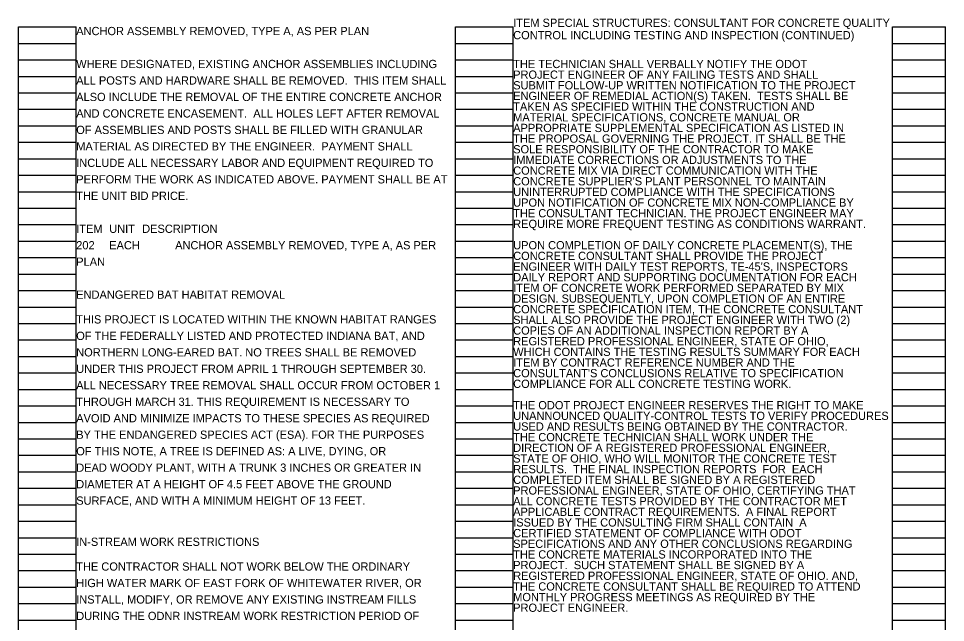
# Model space of a CAD drawing. Extents: x 0 to 78.9, y -24.2 to 22.
# Drawn here: x 61.9 to 77.64, y -13.19 to -2.93 of the extents above; entities that cross this region are included whole.
import ezdxf

# ---------------------------------------------------------------- set-up
doc = ezdxf.new("R2010")
doc.units = 0
doc.layers.add('SH_Data', color=7, linetype='Continuous')
doc.layers.add('SH_Text', color=7, linetype='Continuous')

msp = doc.modelspace()

# ---------------------------------------------------------------- linework, layer by layer
at = {"layer": 'SH_Data'}
for p, q in [((61.904, -23.228), (61.904, -3.068)), ((61.904, -3.068), (62.884, -3.068)), ((62.884, -23.228), (62.884, -3.068)), ((69.324, -23.228), (69.324, -3.068)), ((69.324, -3.068), (70.304, -3.068)), ((70.304, -23.228), (70.304, -3.068)), ((76.744, -23.228), (76.744, -3.068)), ((76.744, -3.068), (77.644, -3.068)), ((77.644, -23.228), (77.644, -3.068)), ((61.904, -3.348), (62.884, -3.348)), ((69.324, -3.348), (70.304, -3.348)), ((76.744, -3.348), (77.644, -3.348)), ((61.904, -3.628), (62.884, -3.628)), ((69.324, -3.628), (70.304, -3.628)), ((76.744, -3.628), (77.644, -3.628)), ((61.904, -3.908), (62.884, -3.908)), ((69.324, -3.908), (70.304, -3.908)), ((76.744, -3.908), (77.644, -3.908)), ((61.904, -4.188), (62.884, -4.188)), ((69.324, -4.188), (70.304, -4.188)), ((76.744, -4.188), (77.644, -4.188)), ((61.904, -4.468), (62.884, -4.468)), ((69.324, -4.468), (70.304, -4.468)), ((76.744, -4.468), (77.644, -4.468)), ((61.904, -4.748), (62.884, -4.748)), ((69.324, -4.748), (70.304, -4.748)), ((76.744, -4.748), (77.644, -4.748)), ((61.904, -5.028), (62.884, -5.028)), ((69.324, -5.028), (70.304, -5.028)), ((76.744, -5.028), (77.644, -5.028)), ((61.904, -5.308), (62.884, -5.308)), ((69.324, -5.308), (70.304, -5.308)), ((76.744, -5.308), (77.644, -5.308)), ((61.904, -5.588), (62.884, -5.588)), ((69.324, -5.588), (70.304, -5.588)), ((76.744, -5.588), (77.644, -5.588)), ((61.904, -5.868), (62.884, -5.868)), ((69.324, -5.868), (70.304, -5.868)), ((76.744, -5.868), (77.644, -5.868)), ((61.904, -6.148), (62.884, -6.148)), ((69.324, -6.148), (70.304, -6.148)), ((76.744, -6.148), (77.644, -6.148)), ((61.904, -6.428), (62.884, -6.428)), ((69.324, -6.428), (70.304, -6.428)), ((76.744, -6.428), (77.644, -6.428)), ((61.904, -6.708), (62.884, -6.708)), ((69.324, -6.708), (70.304, -6.708)), ((76.744, -6.708), (77.644, -6.708)), ((61.904, -6.988), (62.884, -6.988)), ((69.324, -6.988), (70.304, -6.988)), ((76.744, -6.988), (77.644, -6.988)), ((61.904, -7.268), (62.884, -7.268)), ((69.324, -7.268), (70.304, -7.268)), ((76.744, -7.268), (77.644, -7.268)), ((61.904, -7.548), (62.884, -7.548)), ((69.324, -7.548), (70.304, -7.548)), ((76.744, -7.548), (77.644, -7.548)), ((61.904, -7.828), (62.884, -7.828)), ((69.324, -7.828), (70.304, -7.828)), ((76.744, -7.828), (77.644, -7.828)), ((61.904, -8.108), (62.884, -8.108)), ((69.324, -8.108), (70.304, -8.108)), ((76.744, -8.108), (77.644, -8.108)), ((61.904, -8.388), (62.884, -8.388)), ((69.324, -8.388), (70.304, -8.388)), ((76.744, -8.388), (77.644, -8.388)), ((61.904, -8.668), (62.884, -8.668)), ((69.324, -8.668), (70.304, -8.668)), ((76.744, -8.668), (77.644, -8.668)), ((61.904, -8.948), (62.884, -8.948)), ((69.324, -8.948), (70.304, -8.948)), ((76.744, -8.948), (77.644, -8.948)), ((61.904, -9.228), (62.884, -9.228)), ((69.324, -9.228), (70.304, -9.228)), ((76.744, -9.228), (77.644, -9.228)), ((61.904, -9.508), (62.884, -9.508)), ((69.324, -9.508), (70.304, -9.508)), ((76.744, -9.508), (77.644, -9.508)), ((61.904, -9.788), (62.884, -9.788)), ((69.324, -9.788), (70.304, -9.788)), ((76.744, -9.788), (77.644, -9.788)), ((61.904, -10.068), (62.884, -10.068)), ((69.324, -10.068), (70.304, -10.068)), ((76.744, -10.068), (77.644, -10.068)), ((61.904, -10.348), (62.884, -10.348)), ((69.324, -10.348), (70.304, -10.348)), ((76.744, -10.348), (77.644, -10.348)), ((61.904, -10.628), (62.884, -10.628)), ((69.324, -10.628), (70.304, -10.628)), ((76.744, -10.628), (77.644, -10.628)), ((61.904, -10.908), (62.884, -10.908)), ((69.324, -10.908), (70.304, -10.908)), ((76.744, -10.908), (77.644, -10.908)), ((61.904, -11.188), (62.884, -11.188)), ((69.324, -11.188), (70.304, -11.188)), ((76.744, -11.188), (77.644, -11.188)), ((61.904, -11.468), (62.884, -11.468)), ((69.324, -11.468), (70.304, -11.468)), ((76.744, -11.468), (77.644, -11.468)), ((61.904, -11.748), (62.884, -11.748)), ((69.324, -11.748), (70.304, -11.748)), ((76.744, -11.748), (77.644, -11.748)), ((61.904, -12.028), (62.884, -12.028)), ((69.324, -12.028), (70.304, -12.028)), ((76.744, -12.028), (77.644, -12.028)), ((61.904, -12.308), (62.884, -12.308)), ((69.324, -12.308), (70.304, -12.308)), ((76.744, -12.308), (77.644, -12.308)), ((61.904, -12.588), (62.884, -12.588)), ((69.324, -12.588), (70.304, -12.588)), ((76.744, -12.588), (77.644, -12.588)), ((61.904, -12.868), (62.884, -12.868)), ((69.324, -12.868), (70.304, -12.868)), ((76.744, -12.868), (77.644, -12.868)), ((61.904, -13.148), (62.884, -13.148)), ((69.324, -13.148), (70.304, -13.148)), ((76.744, -13.148), (77.644, -13.148))]:
    msp.add_line(p, q, dxfattribs=at)

# ---------------------------------------------------------------- texts
at = {"layer": 'SH_Text'}
for s, p in [('ITEM SPECIAL STRUCTURES: CONSULTANT FOR CONCRETE QUALITY', (70.304, -3.068)), ('ANCHOR ASSEMBLY REMOVED, TYPE A, AS PER PLAN', (62.884, -3.208)), ('CONTROL INCLUDING TESTING AND INSPECTION (CONTINUED)', (70.304, -3.278)), ('WHERE DESIGNATED, EXISTING ANCHOR ASSEMBLIES INCLUDING ', (62.884, -3.768)), ('THE TECHNICIAN SHALL VERBALLY NOTIFY THE ODOT', (70.304, -3.768)), ('ALL POSTS AND HARDWARE SHALL BE REMOVED.  THIS ITEM SHALL ', (62.884, -4.048)), ('PROJECT ENGINEER OF ANY FAILING TESTS AND SHALL', (70.304, -3.949)), ('SUBMIT FOLLOW-UP WRITTEN NOTIFICATION TO THE PROJECT', (70.304, -4.13)), ('ALSO INCLUDE THE REMOVAL OF THE ENTIRE CONCRETE ANCHOR ', (62.884, -4.328)), ('ENGINEER OF REMEDIAL ACTION(S) TAKEN.  TESTS SHALL BE', (70.304, -4.311)), ('TAKEN AS SPECIFIED WITHIN THE CONSTRUCTION AND', (70.304, -4.492)), ('AND CONCRETE ENCASEMENT.  ALL HOLES LEFT AFTER REMOVAL ', (62.884, -4.608)), ('MATERIAL SPECIFICATIONS, CONCRETE MANUAL OR', (70.304, -4.674)), ('APPROPRIATE SUPPLEMENTAL SPECIFICATION AS LISTED IN', (70.304, -4.855)), ('OF ASSEMBLIES AND POSTS SHALL BE FILLED WITH GRANULAR ', (62.884, -4.888)), ('MATERIAL AS DIRECTED BY THE ENGINEER.  PAYMENT SHALL  ', (62.884, -5.168)), ('THE PROPOSAL GOVERNING THE PROJECT. IT SHALL BE THE', (70.304, -5.036)), ('SOLE RESPONSIBILITY OF THE CONTRACTOR TO MAKE', (70.304, -5.217)), ('INCLUDE ALL NECESSARY LABOR AND EQUIPMENT REQUIRED TO ', (62.884, -5.448)), ('IMMEDIATE CORRECTIONS OR ADJUSTMENTS TO THE', (70.304, -5.398)), ('CONCRETE MIX VIA DIRECT COMMUNICATION WITH THE', (70.304, -5.579)), ('PERFORM THE WORK AS INDICATED ABOVE. PAYMENT SHALL BE AT ', (62.884, -5.728)), ("CONCRETE SUPPLIER'S PLANT PERSONNEL TO MAINTAIN", (70.304, -5.761)), ('UNINTERRUPTED COMPLIANCE WITH THE SPECIFICATIONS', (70.304, -5.942)), ('THE UNIT BID PRICE.', (62.884, -6.008)), ('UPON NOTIFICATION OF CONCRETE MIX NON-COMPLIANCE BY', (70.304, -6.123)), ('THE CONSULTANT TECHNICIAN. THE PROJECT ENGINEER MAY', (70.304, -6.304)), ('ITEM', (62.884, -6.568)), ('UNIT', (63.444, -6.568)), ('DESCRIPTION', (64.004, -6.568)), ('REQUIRE MORE FREQUENT TESTING AS CONDITIONS WARRANT.', (70.304, -6.485)), ('202 ', (62.884, -6.848)), ('EACH ', (63.444, -6.848)), ('ANCHOR ASSEMBLY REMOVED, TYPE A, AS PER ', (64.564, -6.848)), ('UPON COMPLETION OF DAILY CONCRETE PLACEMENT(S), THE', (70.304, -6.848)), ('CONCRETE CONSULTANT SHALL PROVIDE THE PROJECT', (70.304, -7.029)), ('PLAN', (62.884, -7.128)), ("ENGINEER WITH DAILY TEST REPORTS, TE-45'S, INSPECTORS", (70.304, -7.21)), ('DAILY REPORT AND SUPPORTING DOCUMENTATION FOR EACH', (70.304, -7.391)), ('ENDANGERED BAT HABITAT REMOVAL', (62.884, -7.688)), ('ITEM OF CONCRETE WORK PERFORMED SEPARATED BY MIX', (70.304, -7.573)), ('DESIGN. SUBSEQUENTLY, UPON COMPLETION OF AN ENTIRE', (70.304, -7.754)), ('CONCRETE SPECIFICATION ITEM, THE CONCRETE CONSULTANT', (70.304, -7.935)), ('THIS PROJECT IS LOCATED WITHIN THE KNOWN HABITAT RANGES', (62.884, -8.108)), ('SHALL ALSO PROVIDE THE PROJECT ENGINEER WITH TWO (2)', (70.304, -8.116)), ('COPIES OF AN ADDITIONAL INSPECTION REPORT BY A', (70.304, -8.297)), ('OF THE FEDERALLY LISTED AND PROTECTED INDIANA BAT, AND', (62.884, -8.388)), ('REGISTERED PROFESSIONAL ENGINEER, STATE OF OHIO,', (70.304, -8.479)), ('NORTHERN LONG-EARED BAT. NO TREES SHALL BE REMOVED', (62.884, -8.668)), ('WHICH CONTAINS THE TESTING RESULTS SUMMARY FOR EACH', (70.304, -8.66)), ('UNDER THIS PROJECT FROM APRIL 1 THROUGH SEPTEMBER 30.', (62.884, -8.948)), ('ITEM BY CONTRACT REFERENCE NUMBER AND THE', (70.304, -8.841)), ("CONSULTANT'S CONCLUSIONS RELATIVE TO SPECIFICATION", (70.304, -9.022)), ('ALL NECESSARY TREE REMOVAL SHALL OCCUR FROM OCTOBER 1', (62.884, -9.228)), ('COMPLIANCE FOR ALL CONCRETE TESTING WORK.', (70.304, -9.203)), ('THROUGH MARCH 31. THIS REQUIREMENT IS NECESSARY TO', (62.884, -9.508)), ('THE ODOT PROJECT ENGINEER RESERVES THE RIGHT TO MAKE', (70.304, -9.566)), ('AVOID AND MINIMIZE IMPACTS TO THESE SPECIES AS REQUIRED', (62.884, -9.788)), ('UNANNOUNCED QUALITY-CONTROL TESTS TO VERIFY PROCEDURES', (70.304, -9.747)), ('USED AND RESULTS BEING OBTAINED BY THE CONTRACTOR. ', (70.304, -9.928)), ('BY THE ENDANGERED SPECIES ACT (ESA). FOR THE PURPOSES', (62.884, -10.068)), ('THE CONCRETE TECHNICIAN SHALL WORK UNDER THE', (70.304, -10.109)), ('OF THIS NOTE, A TREE IS DEFINED AS: A LIVE, DYING, OR', (62.884, -10.348)), ('DIRECTION OF A REGISTERED PROFESSIONAL ENGINEER,', (70.304, -10.29)), ('STATE OF OHIO, WHO WILL MONITOR THE CONCRETE TEST', (70.304, -10.472)), ('DEAD WOODY PLANT, WITH A TRUNK 3 INCHES OR GREATER IN', (62.884, -10.628)), ('RESULTS.  THE FINAL INSPECTION REPORTS  FOR  EACH', (70.304, -10.653)), ('COMPLETED ITEM SHALL BE SIGNED BY A REGISTERED', (70.304, -10.834)), ('DIAMETER AT A HEIGHT OF 4.5 FEET ABOVE THE GROUND', (62.884, -10.908)), ('PROFESSIONAL ENGINEER, STATE OF OHIO, CERTIFYING THAT', (70.304, -11.015)), ('SURFACE, AND WITH A MINIMUM HEIGHT OF 13 FEET.', (62.884, -11.188)), ('ALL CONCRETE TESTS PROVIDED BY THE CONTRACTOR MET', (70.304, -11.196)), ('APPLICABLE CONTRACT REQUIREMENTS.  A FINAL REPORT', (70.304, -11.378)), ('ISSUED BY THE CONSULTING FIRM SHALL CONTAIN  A', (70.304, -11.559)), ('CERTIFIED STATEMENT OF COMPLIANCE WITH ODOT', (70.304, -11.74)), ('IN-STREAM WORK RESTRICTIONS', (62.884, -11.888)), ('SPECIFICATIONS AND ANY OTHER CONCLUSIONS REGARDING', (70.304, -11.921)), ('THE CONCRETE MATERIALS INCORPORATED INTO THE', (70.304, -12.102)), ('THE CONTRACTOR SHALL NOT WORK BELOW THE ORDINARY ', (62.884, -12.308)), ('PROJECT.  SUCH STATEMENT SHALL BE SIGNED BY A', (70.304, -12.283)), ('REGISTERED PROFESSIONAL ENGINEER, STATE OF OHIO. AND,', (70.304, -12.465)), ('HIGH WATER MARK OF EAST FORK OF WHITEWATER RIVER, OR ', (62.884, -12.588)), ('THE CONCRETE CONSULTANT SHALL BE REQUIRED TO ATTEND', (70.304, -12.646)), ('INSTALL, MODIFY, OR REMOVE ANY EXISTING INSTREAM FILLS ', (62.884, -12.868)), ('MONTHLY PROGRESS MEETINGS AS REQUIRED BY THE', (70.304, -12.827)), ('PROJECT ENGINEER.', (70.304, -13.008)), ('DURING THE ODNR INSTREAM WORK RESTRICTION PERIOD OF ', (62.884, -13.148))]:
    msp.add_text(s, height=0.14, dxfattribs=at).set_placement(p)

doc.saveas('drawing.dxf')
